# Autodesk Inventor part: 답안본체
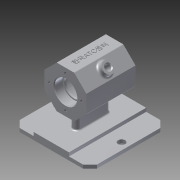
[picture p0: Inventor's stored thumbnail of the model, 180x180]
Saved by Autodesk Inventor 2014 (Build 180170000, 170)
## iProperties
Created: 2018-06
Part Number: 답안본체
Material: Aluminum 6061
Document SubType Name: Modeling
Designer: kh
Density: 2.71 g/cm^3
Appearance: Aluminum - Flat
Mass: 554.035 g
Surface Area: 601.93 cm^2
Volume: 204.441 cm^3
Author: kh
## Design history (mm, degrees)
sketch "Sketch1" dims "d0" = 60
  geometry: L1 (0, 0)-(0, 30); L2 (12.426, 30)-(30, 12.426); L3 (30, 12.426)-(30, -12.426); L4 (30, -12.426)-(12.426, -30); L5 (12.426, -30)-(-12.426, -30); L6 (-12.426, -30)-(-30, -12.426); L7 (-30, -12.426)-(-30, 12.426); L8 (-30, 12.426)-(-12.426, 30); L9 (-12.426, 30)-(12.426, 30); 2 further points
  constraints: 18 end point, 2 coincident, 1 midpoint, 1 vertical, 1 vertical alignment, 19 other
extrude "Extrusion1" new body sketch "Sketch1" stored distance "d1" = 70; taper "d2" = 0 deg
workplane "Work Plane1"
sketch "Sketch2"
  geometry: L1 (-45, 55)-(45, 55); L2 (55, 45)-(55, -45); L3 (45, -55)-(-45, -55); L4 (-55, -45)-(-55, 45); L5 (-55, 55)-(55, -55); L6 (55, 55)-(-55, -55); L7 (-45, 55)-(-55, 45); L8 (-55, -45)-(-45, -55); L9 (45, -55)-(55, -45); L10 (55, 45)-(45, 55); 1 further point
  constraints: 20 end point, 8 point on line, 2 midpoint, 2 parallel, 1 horizontal, 1 perpendicular
  dimensions: "d4" = 110 distance of L5.start L6.start; "d5" = 110 distance of L6.start L5.end; "d6" = 10 distance of L1.start L5.start; "d7" = 10 distance of L4.end L5.start (= d6); "d8" = 10 distance of L4.start L6.end (= d6); "d9" = 10 distance of L3.end L6.end (= d8); "d10" = 10 distance of L3.start L5.end (= d6); "d11" = 10 distance of L2.end L5.end (= d10); "d12" = 10 distance of L2.start L6.start (= d6); "d13" = 10 distance of L1.end L6.start (= d12)
extrude "Extrusion2" join sketch "Sketch2" distance "d14" = 5; taper "d15" = 0 deg
sketch "Sketch3"
  geometry: L1 (45, -55)-(55, -45) reference; L2 (-45, -55)-(45, -55) reference; L3 (-55, -45)-(-45, -55) reference; L4 (-55, 45)-(-55, -45) reference; L5 (-45, 55)-(-55, 45) reference; L6 (45, 55)-(-45, 55) reference; L7 (55, 45)-(45, 55) reference; L8 (55, -45)-(55, 45) reference; L9 (55, 25)-(-55, 25); L10 (-55, 25)-(-55, -25); L11 (-55, -25)-(55, -25); L12 (55, -25)-(55, 25); 1 further point
  constraints: 8 end point, 2 parallel, 2 point on line, 1 horizontal, 1 perpendicular
  dimensions: "d16" = 30 distance between parallel lines of L6 L9; "d17" = 30 distance between parallel lines of L2 L11
extrude "Extrusion3" join sketch "Sketch3" distance "d18" = 5; taper "d19" = 0 deg
sketch "Sketch4"
  geometry: L1 (45, -55)-(55, -45) reference; L2 (-45, -55)-(45, -55) reference; L3 (-55, -45)-(-45, -55) reference; L4 (-55, 45)-(-55, -45) reference; L5 (-45, 55)-(-55, 45) reference; L6 (45, 55)-(-45, 55) reference; L7 (55, 45)-(45, 55) reference; L8 (55, -45)-(55, 45) reference; L9 (-55, 25)-(55, 25) reference; L10 (55, -25)-(-55, -25) reference; L11 (55, 0)-(-55, 0); L12 (0, 25)-(0, -25); L13 (19, 0)-(-19, 0); L14 (19, 5)-(-19, 5); L15 (-19, -5)-(19, -5); A1 r 5 centre (19, 0) between (19, -5) and (19, 5); A2 r 5 centre (-19, 0) between (-19, 5) and (-19, -5); 4 further points
  constraints: 12 end point, 7 midpoint, 4 point on circle, 4 tangent, 2 centre point, 2 coincident, 2 point on line, 1 parallel
  dimensions: "d20" = 10 distance between parallel lines of L15 L14; "d21" = 38 distance of L13.end L13.start
extrude "Extrusion4" join sketch "Sketch4" stored distance "d22" = 5; taper "d23" = 0 deg
workplane "Work Plane2"
sketch "Sketch5"
  geometry: C1 r 8 at (35, 12.426); 1 further point
  constraints: 1 centre point, 1 coincident
  dimensions: "d25" = 16 diameter of C1
extrude "Extrusion5" join sketch "Sketch5" stored distance "d26" = 5; taper "d27" = 0 deg
sketch "Sketch6"
  geometry: L1 (35, 30)-(-35, 30) reference; L2 (-35, 30)-(-35, 12.426) reference; L3 (-35, 12.426)-(-35, -12.426) reference; L4 (-35, -12.426)-(-35, -30) reference; L5 (35, 12.426)-(35, 30) reference; L6 (35, -12.426)-(35, 12.426) reference; L7 (35, -30)-(35, -12.426) reference; L8 (-35, 16)-(-23, 16); L9 (-23, 16)-(-23, 14); L10 (-23, 14)-(-20, 14); L11 (-20, 14)-(-20, 25); L12 (-20, 25)-(20, 25); L13 (20, 25)-(20, 14); L14 (20, 14)-(23, 14); L15 (23, 14)-(23, 16); L16 (23, 16)-(35, 16); L17 (-35, 16)-(-35, 0); L18 (35, 16)-(35, 0); L19 (35, 0)-(-35, 0); 1 further point
  constraints: 24 end point, 6 parallel, 4 equal length, 3 perpendicular, 2 collinear, 2 midpoint, 2 point on line
  dimensions: "d31" = 12 distance between parallel lines of L9 L3; "d32" = 40 distance between parallel lines of L13 L11; "d33" = 32 diameter of L8 L19; "d34" = 50 diameter of L12 L19; "d35" = 28 diameter of L10 L19
revolve "Revolution1" sketch "Sketch6" stored, may be unused: angle "d36" = 90 deg
hole "Hole1" diameter "d39" = 8; stored, may be unused: countersink angle "d43" = 90 deg, drill point angle "d45" = 118 deg; dims "d37" = 10, "d38" = 10, "d40" = 6, "d41" = 4, "d42" = 2, "d44" = 8
sketch "Sketch7"
  geometry: L1 (30, 12.426)-(12.426, 30) reference; L2 (12.426, 30)-(-12.426, 30) reference; L3 (-12.426, 30)-(-30, 12.426) reference; L4 (-30, 12.426)-(-30, -12.426) reference; L5 (-30, -12.426)-(-12.426, -30) reference; L6 (-12.426, -30)-(12.426, -30) reference; L7 (12.426, -30)-(30, -12.426) reference; L8 (30, -12.426)-(30, 12.426) reference; L9 (0, -23)-(0, 23); C1 r 16 at (0, 0) reference; A1 r 23 centre (0, 0) between (-23, 0) and (23, 0); 3 further points
  constraints: 4 point on circle, 3 coincident, 2 end point, 1 centre point, 1 midpoint, 1 parallel
  dimensions: "d46" = 46 diameter of A1
hole "Hole2" sketch "Sketch7" at (-23, 0), (23, 0), (0, 23), (0, -23) diameter "d47" = 3.242; stored, may be unused: countersink angle "d51" = 90 deg, drill point angle "d53" = 118 deg; dims "d48" = 8, "d49" = 4, "d50" = 2, "d52" = 10
mirror "Mirror1"
sketch "Sketch8"
  geometry: L1 (7.276, 5.997)-(62.724, 5.997); L2 (62.724, 5.997)-(62.724, 18.856); L3 (62.724, 18.856)-(7.276, 18.856); L4 (7.276, 18.856)-(7.276, 5.997); L5 (70, 0)-(0, 0) reference; L6 (70, 24.853)-(70, 0) reference; L7 (70, 24.853)-(0, 24.853) reference; L8 (0, 0)-(0, 24.853) reference; L9 (35, 5.997)-(35, 18.856); L10 (7.276, 12.426)-(62.724, 12.426); L11 (10, 37.047)-(10, 33.805) reference; L12 (70, 42.426)-(0, 42.426) reference; 1 further point
  constraints: 4 end point, 4 midpoint, 2 other
  dimensions: "d54" = 35 distance between parallel lines of L9 L8; "d57" = 30 distance between parallel lines of L12 L10
emboss "Emboss1" sketch "Sketch8" dims "d4" = 110, "d5" = 110, "d6" = 10, "d7" = 10 (= d6), "d8" = 10 (= d6), "d9" = 10 (= d8), "d10" = 10 (= d6), "d11" = 10 (= d10), "d12" = 10 (= d6), "d13" = 10 (= d12), "d58" = 0.5, "d59" = 0
hole "Hole3" diameter "d62" = 10; stored, may be unused: countersink angle "d66" = 90 deg, drill point angle "d68" = 118 deg; dims "d60" = 10, "d61" = 55, "d63" = 8, "d64" = 4, "d65" = 2, "d67" = 10
hole "Hole4" diameter "d71" = 10; stored, may be unused: countersink angle "d75" = 90 deg, drill point angle "d77" = 118 deg; dims "d69" = 10, "d70" = 55, "d72" = 8, "d73" = 4, "d74" = 2, "d76" = 10
fillet "Fillet1" dims "d78" = 2
fillet "Fillet2" dims "d79" = 3
fillet "Fillet3" dims "d80" = 0.3
fillet "Fillet4" dims "d81" = 1
fillet "Fillet5" dims "d82" = 3
chamfer "Chamfer1" distance "d83" = 1; stored, may be unused: second distance "d84" = 2, angle "d85" = 45 deg
body "Solid1"
node "Projected Loop1"
node "Projected Loop2"
node "Projected Loop3"
node "Projected Loop4"
other parameters: "d3" = -62, "d24" = 7
